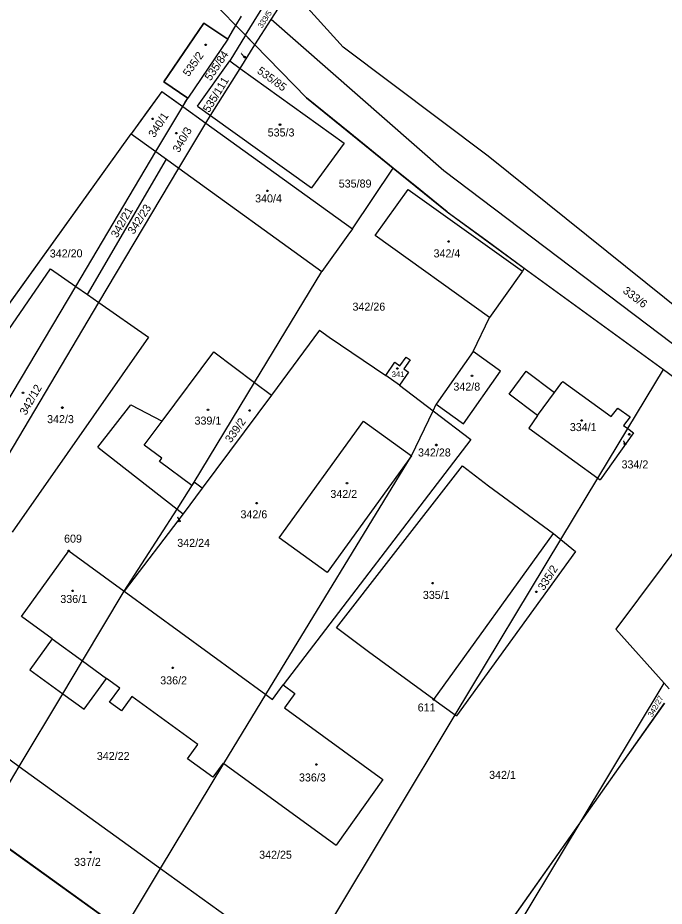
# Model space of a CAD drawing. Extents: x -634640 to -629202, y -1196156 to -1190068.
# Drawn here: x -632441.5 to -632304.1, y -1192469.9 to -1192281.2 of the extents above; entities that cross this region are included whole.
import ezdxf

# ---------------------------------------------------------------- set-up
doc = ezdxf.new("R2010")
doc.units = 0
for name, color, linetype in [('Obvod převzatý', 7, 'Continuous'), ('Obvod šetřený', 7, 'Continuous'), ('Vrstva 1', 7, 'Continuous'), ('Vrstva 2', 7, 'Continuous'), ('Vrstva 4', 7, 'Continuous'), ('Vrstva 5', 7, 'Continuous'), ('Vrstva 7', 7, 'Continuous'), ('Vrstva 8', 7, 'Continuous')]:
    doc.layers.add(name, color=color, linetype=linetype)

msp = doc.modelspace()

# ---------------------------------------------------------------- linework, layer by layer
at = {"layer": 'Obvod převzatý'}
for points in [[(-632396.88, -1192285.77), (-632401.94, -1192282.34), (-632406.18, -1192288.59), (-632410.42, -1192294.84), (-632405.36, -1192298.28)], [(-632410.87, -1192296.86), (-632414.13, -1192301.36), (-632417.39, -1192305.86)], [(-632410.87, -1192296.86), (-632408.645, -1192298.46), (-632406.42, -1192300.06), (-632405.89, -1192299.17), (-632405.36, -1192298.28)], [(-632350.27, -1192322.41), (-632355.98, -1192317.785), (-632361.69, -1192313.16), (-632370.93, -1192305.68), (-632380.17, -1192298.2)]]:
    msp.add_lwpolyline(points, dxfattribs=at)
at = {"layer": 'Obvod šetřený'}
for points in [[(-632396.88, -1192285.77), (-632396, -1192284.305), (-632395.12, -1192282.84), (-632394.1, -1192283.89), (-632393.08, -1192284.94), (-632392.08, -1192285.97), (-632391.08, -1192287), (-632385.625, -1192292.6), (-632380.17, -1192298.2)], [(-632445.42, -1192344.855), (-632417.39, -1192305.86)], [(-632350.27, -1192322.41), (-632342.065, -1192328.395), (-632333.86, -1192334.38), (-632319.09, -1192345.155), (-632304.32, -1192355.93), (-632291.955, -1192364.95), (-632279.59, -1192373.97)], [(-632304.09, -1192426.76), (-632313.05, -1192439.46), (-632343.995, -1192483.305), (-632365.98, -1192514.45), (-632389.31, -1192496.99), (-632397.68, -1192490.725), (-632406.05, -1192484.46), (-632412.575, -1192479.78), (-632419.1, -1192475.1), (-632434.11, -1192464.33), (-632449.12, -1192453.56)]]:
    msp.add_lwpolyline(points, dxfattribs=at)
at = {"layer": 'Vrstva 1'}
for p, q in [((-632393.08, -1192284.94), (-632385.61, -1192272.81)), ((-632387.64, -1192281.59), (-632383.53, -1192275.11)), ((-632383.53, -1192275.11), (-632372.32, -1192287.46)), ((-632401.63, -1192276.16), (-632395.12, -1192282.84)), ((-632395.12, -1192282.84), (-632393.93, -1192280.85)), ((-632391.08, -1192287), (-632387.64, -1192281.59)), ((-632350.96, -1192313.7), (-632387.64, -1192281.59)), ((-632410.42, -1192294.84), (-632401.94, -1192282.34)), ((-632401.94, -1192282.34), (-632396.88, -1192285.77)), ((-632396.88, -1192285.77), (-632395.12, -1192282.84)), ((-632395.12, -1192282.84), (-632393.08, -1192284.94)), ((-632393.08, -1192284.94), (-632396.42, -1192290.39)), ((-632393.08, -1192284.94), (-632391.08, -1192287)), ((-632396.88, -1192285.77), (-632405.36, -1192298.28)), ((-632394.23, -1192291.97), (-632391.08, -1192287)), ((-632391.08, -1192287), (-632380.17, -1192298.2)), ((-632341.56, -1192310.6), (-632372.32, -1192287.46)), ((-632403.31, -1192299.98), (-632396.42, -1192290.39)), ((-632396.42, -1192290.39), (-632394.23, -1192291.97)), ((-632400.56, -1192301.94), (-632394.23, -1192291.97)), ((-632394.23, -1192291.97), (-632372.1, -1192307.88)), ((-632405.36, -1192298.28), (-632410.42, -1192294.84)), ((-632410.87, -1192296.86), (-632417.39, -1192305.86)), ((-632410.87, -1192296.86), (-632406.42, -1192300.06)), ((-632406.42, -1192300.06), (-632405.36, -1192298.28)), ((-632380.17, -1192298.2), (-632361.69, -1192313.16)), ((-632412.13, -1192309.65), (-632406.42, -1192300.06)), ((-632406.42, -1192300.06), (-632401.54, -1192303.58)), ((-632403.31, -1192299.98), (-632400.56, -1192301.94)), ((-632401.54, -1192303.58), (-632400.56, -1192301.94)), ((-632400.56, -1192301.94), (-632379.04, -1192317.31)), ((-632407.25, -1192313.17), (-632401.54, -1192303.58)), ((-632401.54, -1192303.58), (-632370.38, -1192326.03)), ((-632473.45, -1192383.85), (-632417.39, -1192305.86)), ((-632417.39, -1192305.86), (-632412.13, -1192309.65)), ((-632372.1, -1192307.88), (-632379.04, -1192317.31)), ((-632429.16, -1192338.28), (-632412.13, -1192309.65)), ((-632412.13, -1192309.65), (-632409.9, -1192311.26)), ((-632426.7, -1192340), (-632409.9, -1192311.26)), ((-632409.9, -1192311.26), (-632407.25, -1192313.17)), ((-632257.63, -1192378.06), (-632341.56, -1192310.6)), ((-632424.24, -1192341.72), (-632407.25, -1192313.17)), ((-632407.25, -1192313.17), (-632376.87, -1192335.08)), ((-632370.38, -1192326.03), (-632361.69, -1192313.16)), ((-632361.69, -1192313.16), (-632350.27, -1192322.41)), ((-632261.68, -1192381.3), (-632350.96, -1192313.7)), ((-632365.56, -1192327.43), (-632358.51, -1192317.66)), ((-632358.51, -1192317.66), (-632334.26, -1192335.05)), ((-632350.27, -1192322.41), (-632333.86, -1192334.38)), ((-632370.38, -1192326.03), (-632371.34, -1192327.37)), ((-632371.34, -1192327.37), (-632376.87, -1192335.08)), ((-632341.29, -1192344.84), (-632365.56, -1192327.43)), ((-632333.86, -1192334.38), (-632334.26, -1192335.05)), ((-632333.86, -1192334.38), (-632304.32, -1192355.93)), ((-632463.27, -1192376), (-632434.51, -1192334.54)), ((-632434.51, -1192334.54), (-632429.16, -1192338.28)), ((-632391.15, -1192358.68), (-632376.87, -1192335.08)), ((-632334.26, -1192335.05), (-632341.29, -1192344.84)), ((-632455.04, -1192381.76), (-632429.16, -1192338.28)), ((-632429.16, -1192338.28), (-632426.7, -1192340)), ((-632426.7, -1192340), (-632424.24, -1192341.72)), ((-632450.12, -1192385.2), (-632424.24, -1192341.72)), ((-632424.24, -1192341.72), (-632413.73, -1192349.07)), ((-632344.71, -1192352.1), (-632341.29, -1192344.84)), ((-632377.37, -1192347.58), (-632387.6, -1192361.35)), ((-632377.37, -1192347.58), (-632375.34, -1192349.04)), ((-632413.73, -1192349.07), (-632442.64, -1192390.43)), ((-632375.34, -1192349.04), (-632363.31, -1192357.18)), ((-632410.8, -1192366.9), (-632399.8, -1192352.16)), ((-632399.8, -1192352.16), (-632391.15, -1192358.68)), ((-632360.32, -1192355.17), (-632358.97, -1192353.3)), ((-632358.97, -1192353.3), (-632358.08, -1192353.88)), ((-632344.71, -1192352.1), (-632352.59, -1192363.3)), ((-632338.91, -1192356.24), (-632344.71, -1192352.1)), ((-632363.31, -1192357.18), (-632361.4, -1192354.38)), ((-632361.4, -1192354.38), (-632360.32, -1192355.17)), ((-632358.08, -1192353.88), (-632359.45, -1192355.8)), ((-632358.49, -1192356.5), (-632360.35, -1192359.26)), ((-632359.45, -1192355.8), (-632358.49, -1192356.5)), ((-632346.79, -1192367.45), (-632338.91, -1192356.24)), ((-632337.08, -1192361.16), (-632333.44, -1192356.3)), ((-632333.44, -1192356.3), (-632327.44, -1192360.79)), ((-632311.86, -1192368.45), (-632304.32, -1192355.93)), ((-632304.32, -1192355.93), (-632279.59, -1192373.97)), ((-632403.97, -1192379.86), (-632391.15, -1192358.68)), ((-632391.15, -1192358.68), (-632387.6, -1192361.35)), ((-632360.35, -1192359.26), (-632363.31, -1192357.18)), ((-632327.44, -1192360.79), (-632325.89, -1192358.69)), ((-632325.89, -1192358.69), (-632325.71, -1192358.44)), ((-632325.71, -1192358.44), (-632315.38, -1192365.91)), ((-632360.35, -1192359.26), (-632353.25, -1192364.67)), ((-632387.6, -1192361.35), (-632402.29, -1192381.11)), ((-632331.08, -1192365.66), (-632337.08, -1192361.16)), ((-632424.47, -1192372.41), (-632417.45, -1192363.44)), ((-632417.45, -1192363.44), (-632410.8, -1192366.9)), ((-632353.25, -1192364.67), (-632352.59, -1192363.3)), ((-632352.59, -1192363.3), (-632346.79, -1192367.45)), ((-632315.38, -1192365.91), (-632313.96, -1192364.1)), ((-632313.96, -1192364.1), (-632311.39, -1192366)), ((-632357.86, -1192374.27), (-632353.25, -1192364.67)), ((-632353.25, -1192364.67), (-632345.19, -1192370.8)), ((-632331.08, -1192365.66), (-632332.87, -1192368.37)), ((-632311.39, -1192366), (-632312.79, -1192367.78)), ((-632385.91, -1192391.69), (-632368.03, -1192366.92)), ((-632368.03, -1192366.92), (-632357.86, -1192374.27)), ((-632332.87, -1192368.37), (-632318.23, -1192379.02)), ((-632312.79, -1192367.78), (-632311.86, -1192368.45)), ((-632318.23, -1192379.02), (-632311.86, -1192368.45)), ((-632310.63, -1192369.34), (-632317.73, -1192379.38)), ((-632311.86, -1192368.45), (-632310.63, -1192369.34)), ((-632345.19, -1192370.8), (-632385.08, -1192422.86)), ((-632424.47, -1192372.41), (-632407.65, -1192385.58)), ((-632388.77, -1192424.93), (-632357.86, -1192374.27)), ((-632357.86, -1192374.27), (-632375.75, -1192399.03)), ((-632362.15, -1192395.87), (-632346.99, -1192376.36)), ((-632346.99, -1192376.36), (-632341.44, -1192380.64)), ((-632326.08, -1192392.05), (-632318.23, -1192379.02)), ((-632318.23, -1192379.02), (-632317.73, -1192379.38)), ((-632407.65, -1192385.58), (-632403.97, -1192379.86)), ((-632402.29, -1192381.11), (-632406.36, -1192386.59)), ((-632341.44, -1192380.64), (-632327.66, -1192390.75)), ((-632291.71, -1192380.67), (-632314.41, -1192411.03)), ((-632418.88, -1192403.01), (-632407.65, -1192385.58)), ((-632406.36, -1192386.59), (-632418.88, -1192403.01)), ((-632407.65, -1192385.58), (-632406.36, -1192386.59)), ((-632327.66, -1192390.75), (-632326.08, -1192392.05)), ((-632375.75, -1192399.03), (-632385.91, -1192391.69)), ((-632348.52, -1192429.29), (-632326.08, -1192392.05)), ((-632326.08, -1192392.05), (-632322.99, -1192394.59)), ((-632440.69, -1192408.39), (-632430.65, -1192394.44)), ((-632430.65, -1192394.44), (-632418.88, -1192403.01)), ((-632322.99, -1192394.59), (-632348.27, -1192429.47)), ((-632373.74, -1192410.8), (-632362.15, -1192395.87)), ((-632427.73, -1192417.8), (-632418.88, -1192403.01)), ((-632418.88, -1192403.01), (-632388.77, -1192424.93)), ((-632434.14, -1192413.15), (-632440.69, -1192408.39)), ((-632366.97, -1192415.86), (-632373.74, -1192410.8)), ((-632314.41, -1192411.03), (-632304.17, -1192422.54)), ((-632434.14, -1192413.15), (-632438.89, -1192419.7)), ((-632353.1, -1192425.98), (-632366.97, -1192415.86)), ((-632431.9, -1192424.77), (-632427.73, -1192417.8)), ((-632438.89, -1192419.7), (-632431.9, -1192424.77)), ((-632427.36, -1192428.07), (-632422.6, -1192421.52)), ((-632419.79, -1192423.56), (-632422.6, -1192421.52)), ((-632387.34, -1192425.97), (-632385.08, -1192422.86)), ((-632385.08, -1192422.86), (-632382.59, -1192424.7)), ((-632322.01, -1192452.16), (-632304.17, -1192422.54)), ((-632304.17, -1192422.54), (-632303.1, -1192423.75)), ((-632441.15, -1192440.23), (-632431.9, -1192424.77)), ((-632431.9, -1192424.77), (-632427.36, -1192428.07)), ((-632421.98, -1192426.58), (-632419.79, -1192423.56)), ((-632397.71, -1192439.59), (-632388.77, -1192424.93)), ((-632388.77, -1192424.93), (-632387.34, -1192425.97)), ((-632382.59, -1192424.7), (-632384.84, -1192427.79)), ((-632419.46, -1192428.4), (-632421.98, -1192426.58)), ((-632417.27, -1192425.39), (-632419.46, -1192428.4)), ((-632403.26, -1192435.56), (-632417.27, -1192425.39)), ((-632353.1, -1192425.98), (-632348.52, -1192429.29)), ((-632322.01, -1192452.16), (-632304.09, -1192426.76)), ((-632384.84, -1192427.79), (-632363.91, -1192443.02)), ((-632381.19, -1192483.51), (-632348.52, -1192429.29)), ((-632348.52, -1192429.29), (-632348.27, -1192429.47)), ((-632405.45, -1192438.57), (-632403.26, -1192435.56)), ((-632445.84, -1192436.85), (-632441.15, -1192440.23)), ((-632411.14, -1192461.87), (-632397.71, -1192439.59)), ((-632400.03, -1192442.5), (-632405.45, -1192438.57)), ((-632397.85, -1192439.49), (-632400.03, -1192442.5)), ((-632397.85, -1192439.49), (-632397.71, -1192439.59)), ((-632397.71, -1192439.59), (-632373.84, -1192456.91)), ((-632449.12, -1192453.56), (-632441.15, -1192440.23)), ((-632441.15, -1192440.23), (-632411.14, -1192461.87)), ((-632363.91, -1192443.02), (-632373.84, -1192456.91)), ((-632434.53, -1192638.9), (-632322.01, -1192452.16)), ((-632365.98, -1192514.45), (-632322.01, -1192452.16)), ((-632449.12, -1192453.56), (-632419.1, -1192475.1)), ((-632419.1, -1192475.1), (-632411.14, -1192461.87)), ((-632411.14, -1192461.87), (-632397.01, -1192472.06))]:
    msp.add_line(p, q, dxfattribs=at)
at = {"layer": 'Vrstva 4'}
for p, q in [((-632331.08, -1192365.66), (-632327.44, -1192360.79)), ((-632414.62, -1192371.98), (-632410.8, -1192366.9)), ((-632410.86, -1192374.76), (-632414.62, -1192371.98)), ((-632411.39, -1192375.49), (-632410.86, -1192374.76)), ((-632404.5, -1192380.58), (-632411.39, -1192375.49)), ((-632403.97, -1192379.86), (-632404.5, -1192380.58)), ((-632402.29, -1192381.11), (-632403.97, -1192379.86)), ((-632353.1, -1192425.98), (-632327.66, -1192390.75)), ((-632434.14, -1192413.15), (-632427.73, -1192417.8)), ((-632427.73, -1192417.8), (-632422.6, -1192421.52))]:
    msp.add_line(p, q, dxfattribs=at)
at = {"layer": 'Vrstva 5'}
for points in [[(-632401.47, -1192286.83), (-632401.38, -1192286.98), (-632401.47, -1192287.13), (-632401.65, -1192287.13), (-632401.74, -1192286.98), (-632401.65, -1192286.83), (-632401.47, -1192286.83)], [(-632412.76, -1192302.56), (-632412.67, -1192302.71), (-632412.76, -1192302.86), (-632412.94, -1192302.86), (-632413.03, -1192302.71), (-632412.94, -1192302.56), (-632412.76, -1192302.56)], [(-632385.69, -1192303.78), (-632385.6, -1192303.93), (-632385.69, -1192304.08), (-632385.87, -1192304.08), (-632385.96, -1192303.93), (-632385.87, -1192303.78), (-632385.69, -1192303.78)], [(-632407.7, -1192305.57), (-632407.61, -1192305.72), (-632407.7, -1192305.87), (-632407.88, -1192305.87), (-632407.97, -1192305.72), (-632407.88, -1192305.57), (-632407.7, -1192305.57)], [(-632388.34, -1192317.8), (-632388.25, -1192317.95), (-632388.34, -1192318.1), (-632388.52, -1192318.1), (-632388.61, -1192317.95), (-632388.52, -1192317.8), (-632388.34, -1192317.8)], [(-632349.87, -1192328.57), (-632349.78, -1192328.72), (-632349.87, -1192328.87), (-632350.05, -1192328.87), (-632350.14, -1192328.72), (-632350.05, -1192328.57), (-632349.87, -1192328.57)], [(-632360.74, -1192355.57), (-632360.65, -1192355.72), (-632360.74, -1192355.87), (-632360.92, -1192355.87), (-632361.01, -1192355.72), (-632360.92, -1192355.57), (-632360.74, -1192355.57)], [(-632344.89, -1192357.13), (-632344.8, -1192357.28), (-632344.89, -1192357.43), (-632345.07, -1192357.43), (-632345.16, -1192357.28), (-632345.07, -1192357.13), (-632344.89, -1192357.13)], [(-632440.29, -1192360.75), (-632440.2, -1192360.9), (-632440.29, -1192361.05), (-632440.47, -1192361.05), (-632440.56, -1192360.9), (-632440.47, -1192360.75), (-632440.29, -1192360.75)], [(-632431.93, -1192363.87), (-632431.84, -1192364.02), (-632431.93, -1192364.17), (-632432.11, -1192364.17), (-632432.2, -1192364.02), (-632432.11, -1192363.87), (-632431.93, -1192363.87)], [(-632400.98, -1192364.32), (-632400.89, -1192364.47), (-632400.98, -1192364.62), (-632401.16, -1192364.62), (-632401.25, -1192364.47), (-632401.16, -1192364.32), (-632400.98, -1192364.32)], [(-632392.15, -1192364.5), (-632392.06, -1192364.65), (-632392.15, -1192364.8), (-632392.33, -1192364.8), (-632392.42, -1192364.65), (-632392.33, -1192364.5), (-632392.15, -1192364.5)], [(-632321.58, -1192366.58), (-632321.49, -1192366.73), (-632321.58, -1192366.88), (-632321.76, -1192366.88), (-632321.85, -1192366.73), (-632321.76, -1192366.58), (-632321.58, -1192366.58)], [(-632311.48, -1192369.53), (-632311.39, -1192369.68), (-632311.48, -1192369.83), (-632311.66, -1192369.83), (-632311.75, -1192369.68), (-632311.66, -1192369.53), (-632311.48, -1192369.53)], [(-632352.46, -1192371.81), (-632352.37, -1192371.96), (-632352.46, -1192372.11), (-632352.64, -1192372.11), (-632352.73, -1192371.96), (-632352.64, -1192371.81), (-632352.46, -1192371.81)], [(-632371.43, -1192379.93), (-632371.34, -1192380.08), (-632371.43, -1192380.23), (-632371.61, -1192380.23), (-632371.7, -1192380.08), (-632371.61, -1192379.93), (-632371.43, -1192379.93)], [(-632390.64, -1192384.14), (-632390.55, -1192384.29), (-632390.64, -1192384.44), (-632390.82, -1192384.44), (-632390.91, -1192384.29), (-632390.82, -1192384.14), (-632390.64, -1192384.14)], [(-632353.27, -1192401.15), (-632353.18, -1192401.3), (-632353.27, -1192401.45), (-632353.45, -1192401.45), (-632353.54, -1192401.3), (-632353.45, -1192401.15), (-632353.27, -1192401.15)], [(-632429.76, -1192402.75), (-632429.67, -1192402.9), (-632429.76, -1192403.05), (-632429.94, -1192403.05), (-632430.03, -1192402.9), (-632429.94, -1192402.75), (-632429.76, -1192402.75)], [(-632331.21, -1192403.01), (-632331.12, -1192403.16), (-632331.21, -1192403.31), (-632331.39, -1192403.31), (-632331.48, -1192403.16), (-632331.39, -1192403.01), (-632331.21, -1192403.01)], [(-632408.46, -1192419.12), (-632408.37, -1192419.27), (-632408.46, -1192419.42), (-632408.64, -1192419.42), (-632408.73, -1192419.27), (-632408.64, -1192419.12), (-632408.46, -1192419.12)], [(-632377.93, -1192439.65), (-632377.84, -1192439.8), (-632377.93, -1192439.95), (-632378.11, -1192439.95), (-632378.2, -1192439.8), (-632378.11, -1192439.65), (-632377.93, -1192439.65)], [(-632425.93, -1192458.28), (-632425.84, -1192458.43), (-632425.93, -1192458.58), (-632426.11, -1192458.58), (-632426.2, -1192458.43), (-632426.11, -1192458.28), (-632425.93, -1192458.28)]]:
    msp.add_lwpolyline(points, dxfattribs=at)
at = {"layer": 'Vrstva 7'}
for p, q in [((-632394.02, -1192288.8), (-632393.28, -1192289.57)), ((-632312.78, -1192371.07), (-632312.47, -1192371.73)), ((-632407.57, -1192387.2), (-632407.15, -1192388.1))]:
    msp.add_line(p, q, dxfattribs=at)
for points in [[(-632393.241, -1192289.741), (-632393.41, -1192289.695), (-632393.449, -1192289.524), (-632393.319, -1192289.399), (-632393.15, -1192289.445), (-632393.111, -1192289.616), (-632393.241, -1192289.741)], [(-632312.489, -1192371.904), (-632312.633, -1192371.806), (-632312.615, -1192371.632), (-632312.451, -1192371.556), (-632312.307, -1192371.654), (-632312.325, -1192371.828), (-632312.489, -1192371.904)], [(-632407.168, -1192388.274), (-632407.313, -1192388.176), (-632407.295, -1192388.002), (-632407.132, -1192387.926), (-632406.987, -1192388.024), (-632407.005, -1192388.198), (-632407.168, -1192388.274)]]:
    msp.add_lwpolyline(points, dxfattribs=at)
at = {"layer": 'Vrstva 8'}
for points in [[(-632430.56, -1192394.29), (-632430.47, -1192394.44), (-632430.56, -1192394.59), (-632430.74, -1192394.59), (-632430.83, -1192394.44), (-632430.74, -1192394.29), (-632430.56, -1192394.29)], [(-632353.01, -1192425.83), (-632352.92, -1192425.98), (-632353.01, -1192426.13), (-632353.19, -1192426.13), (-632353.28, -1192425.98), (-632353.19, -1192425.83), (-632353.01, -1192425.83)]]:
    msp.add_lwpolyline(points, dxfattribs=at)

# ---------------------------------------------------------------- texts
at = {"layer": 'Vrstva 2'}
for s, height, rotation, p in [('333/5', 1.19, 56.72282, (-632389.599, -1192283.521)), ('535/2', 1.7, 54.77476, (-632405.173, -1192293.856)), ('535/84', 1.7, 55.6342, (-632400.516, -1192294.734)), ('535/85', 0.1, 56.72282, (-632394.012, -1192288.788)), ('535/111', 1.7, 58.61358, (-632400.826, -1192301.475)), ('340/1', 1.7, 57.0093, (-632412.451, -1192306.811)), ('340/3', 1.7, 60.27516, (-632407.232, -1192310.004)), ('342/23', 1.7, 56.72282, (-632416.85, -1192327.352)), ('342/21', 1.7, 60.73353, (-632420.344, -1192328.083)), ('342/20', 1.7, 0.45837, (-632434.673, -1192332.138)), ('333/6', 1.7, 322.40335, (-632313.062, -1192339.495)), ('342/12', 1.7, 60.27516, (-632439.732, -1192365.774)), ('339/2', 1.7, 54.88936, (-632396.203, -1192371.636)), ('334/2', 0.1, 53.28508, (-632312.772, -1192371.059)), ('342/24', 0.1, 53.17048, (-632407.562, -1192387.189)), ('335/2', 1.7, 57.58226, (-632329.695, -1192402.98)), ('342/27', 1.19, 59.81679, (-632306.676, -1192429.836))]:
    msp.add_text(s, height=height, rotation=rotation, dxfattribs=at).set_placement(p)
for s, height, p in [('535/3', 1.7, (-632388.383, -1192306.43)), ('535/89', 1.7, (-632373.283, -1192317.28)), ('340/4', 1.7, (-632391.053, -1192320.43)), ('342/4', 1.7, (-632353.143, -1192332.11)), ('342/26', 1.7, (-632370.363, -1192343.42)), ('341', 1.19, (-632362.014, -1192357.52)), ('342/8', 1.7, (-632348.923, -1192360.4)), ('342/3', 1.7, (-632435.253, -1192367.31)), ('339/1', 1.7, (-632403.923, -1192367.62)), ('334/1', 1.7, (-632324.183, -1192369)), ('342/28', 1.7, (-632356.443, -1192374.39)), ('342/2', 1.7, (-632375.063, -1192383.2)), ('342/6', 1.7, (-632394.163, -1192387.52)), ('336/1', 1.7, (-632432.443, -1192405.5)), ('335/1', 1.7, (-632355.413, -1192404.64)), ('336/2', 1.7, (-632411.213, -1192422.79)), ('342/22', 1.7, (-632424.683, -1192438.84)), ('336/3', 1.7, (-632381.733, -1192443.41)), ('342/1', 1.7, (-632341.333, -1192442.86)), ('342/25', 1.7, (-632390.193, -1192459.82)), ('337/2', 1.7, (-632429.523, -1192461.34))]:
    msp.add_text(s, height=height, dxfattribs=at).set_placement(p)
at = {"layer": 'Vrstva 7'}
msp.add_text('535/85', height=1.7, rotation=324.00763, dxfattribs=at).set_placement((-632390.777, -1192292.845))
for s, p in [('334/2', (-632313.203, -1192376.92)), ('342/24', (-632407.593, -1192393.59))]:
    msp.add_text(s, height=1.7, dxfattribs=at).set_placement(p)
at = {"layer": 'Vrstva 8'}
for s, p in [('609', (-632431.643, -1192392.69)), ('611', (-632356.513, -1192428.54))]:
    msp.add_text(s, height=1.7, dxfattribs=at).set_placement(p)

doc.saveas('drawing.dxf')
